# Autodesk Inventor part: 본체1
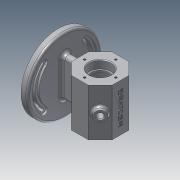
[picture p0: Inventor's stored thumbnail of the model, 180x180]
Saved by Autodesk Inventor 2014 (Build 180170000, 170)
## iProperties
Created: 2017-06
Part Number: 본체1
Material: 알루미늄 6061
Document SubType Name: Modeling
Designer: Administrator
Mass: 555.974 g
Surface Area: 564.009 cm^2
Volume: 205.157 cm^3
Density: 2.71 g/cm^3
Appearance: 알루미늄 - 평지
Author: Administrator
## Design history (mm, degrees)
sketch "스케치1"
  geometry: L1 (12.426, 30)-(30, 12.426); L2 (30, 12.426)-(30, -12.426); L3 (30, -12.426)-(12.426, -30); L4 (12.426, -30)-(-12.426, -30); L5 (-12.426, -30)-(-30, -12.426); L6 (-30, -12.426)-(-30, 12.426); L7 (-30, 12.426)-(-12.426, 30); L8 (-12.426, 30)-(12.426, 30); A1 r 30 centre (0, 0) between (0, 30) and (0, -30); 3 further points
  constraints: 16 end point, 4 midpoint, 4 point on circle, 4 tangent, 1 centre point, 1 coincident, 1 horizontal alignment
  dimensions: "d0" = 60 diameter of A1; "d74" = 60 distance between parallel lines of L3 L7; "d75" = 60 distance between parallel lines of L1 L5; "d76" = 24.85281 distance of L1.start L7.end; "d77" = 17.57359 horizontal distance of L6.end L7.end
extrude "돌출1" new body sketch "스케치1" stored distance "d1" = 70; taper "d2" = 0 deg
node "작업 평면1"
sketch "스케치3"
  geometry: L1 (0, 24.853)-(0, 42.426) reference; L2 (0, 42.426)-(70, 42.426) reference; 2 further points
  constraints: 1 other
  dimensions: "d4" = 35 distance from line of L1 point (35, 12.426); "d5" = 30 distance from line of L2 point (35, 12.426)
feature "엠보싱1" sketch "스케치3" dims "d6" = 0.5, "d7" = 0
sketch "스케치4"
  geometry: C1 r 8 at (12.426, 35); 1 further point
  constraints: 1 centre point, 1 coincident
  dimensions: "d8" = 16 diameter of C1
extrude "돌출2" join sketch "스케치4" distance "d9" = 7; taper "d10" = 0 deg
node "작업 평면2"
sketch "스케치6"
  geometry: C1 r 55 at (0, 0); 1 further point
  constraints: 1 centre point, 1 coincident
  dimensions: "d12" = 110 diameter of C1
extrude "돌출3" join sketch "스케치6" distance "d13" = 10; taper "d14" = 0 deg
sketch "스케치7"
  geometry: L1 (17.688, 29)-(52, 29); L2 (52, 29)-(52, -29); L3 (52, -29)-(17.688, -29); L4 (17.688, -29)-(17.688, 29); L5 (52, 55)-(52, -55) reference; 3 further points
  constraints: 8 end point, 2 coincident, 2 midpoint, 2 parallel, 1 horizontal, 1 perpendicular
  dimensions: "d15" = 58 distance between parallel lines of L3 L1
extrude "돌출4" join sketch "스케치7" stored distance "d16" = 10; taper "d17" = 0 deg
fillet "모깎기1" dims "d18" = 5
fillet "모깎기2" dims "d19" = 5
fillet "모깎기3" dims "d20" = 5
sketch "스케치9"
  geometry: L1 (0, 0)-(30.406, 30.406); L2 (0, 0)-(-30.406, 30.406); L3 (0, 0)-(30.406, -30.406); L4 (0, 0)-(-30.406, -30.406); C1 r 55 at (0, 0) reference; A1 r 43 centre (0, 0) between (30.406, 30.406) and (-30.406, 30.406); A2 r 48 centre (0, 0) between (33.941, 33.941) and (-33.941, 33.941); A3 r 38 centre (0, 0) between (26.87, 26.87) and (-26.87, 26.87); A4 r 5 centre (30.406, 30.406) between (26.87, 26.87) and (33.941, 33.941); A5 r 5 centre (-30.406, 30.406) between (-33.941, 33.941) and (-26.87, 26.87); A6 r 43 centre (0, 0) between (-30.406, -30.406) and (30.406, -30.406); A7 r 48 centre (0, 0) between (-33.941, -33.941) and (33.941, -33.941); A8 r 38 centre (0, 0) between (-26.87, -26.87) and (26.87, -26.87); A9 r 5 centre (-30.406, -30.406) between (-26.87, -26.87) and (-33.941, -33.941); A10 r 5 centre (30.406, -30.406) between (33.941, -33.941) and (26.87, -26.87); 2 further points
  constraints: 22 point on circle, 10 centre point, 8 end point, 8 tangent, 2 coincident, 2 vertical alignment
  dimensions: "d26" = 90 deg angle of L1 L2; "d27" = 90 deg angle of L4 L3; "d29" = 43 radius of A6; "d30" = 38 radius of A3; "d31" = 38 radius of A8; "d73" = 86 diameter of A1
extrude "돌출5" cut sketch "스케치9" distance "d32" = 3; taper "d33" = 0 deg
sketch "스케치10"
  geometry: C1 r 55 at (0, 0) reference; A1 r 5 centre (-30.406, 30.406) between (-33.941, 33.941) and (-26.87, 26.87) reference; A2 r 5 centre (30.406, 30.406) between (26.87, 26.87) and (33.941, 33.941) reference; A3 r 5 centre (30.406, -30.406) between (33.941, -33.941) and (26.87, -26.87) reference; A4 r 5 centre (-30.406, -30.406) between (-26.87, -26.87) and (-33.941, -33.941) reference; A5 r 43 centre (0, 0) between (30.406, 30.406) and (-30.406, 30.406); A6 r 45 centre (0, 0) between (31.82, 31.82) and (-31.82, 31.82); A7 r 41 centre (0, 0) between (28.991, 28.991) and (-28.991, 28.991); A8 r 2 centre (30.406, 30.406) between (28.991, 28.991) and (31.82, 31.82); A9 r 2 centre (-30.406, 30.406) between (-31.82, 31.82) and (-28.991, 28.991); A10 r 43 centre (0, 0) between (-30.406, -30.406) and (30.406, -30.406); A11 r 45 centre (0, 0) between (-31.82, -31.82) and (31.82, -31.82); A12 r 41 centre (0, 0) between (-28.991, -28.991) and (28.991, -28.991); A13 r 2 centre (-30.406, -30.406) between (-28.991, -28.991) and (-31.82, -31.82); A14 r 2 centre (30.406, -30.406) between (31.82, -31.82) and (28.991, -28.991)
  constraints: 20 point on circle, 10 centre point, 8 tangent, 2 coincident
  dimensions: "d34" = 2 radius of A9; "d35" = 2 radius of A13
extrude "돌출6" cut sketch "스케치10" distance "d36" = 10; taper "d37" = 0 deg
sketch "스케치13"
  geometry: L1 (0, -35)-(-16, -35); L2 (-16, -35)-(-16, -23); L3 (-16, -23)-(0, -23); L4 (0, -23)-(0, -35); L5 (0, -23)-(-14, -23); L6 (-14, -23)-(-14, -20); L7 (-14, -20)-(0, -20); L8 (0, -20)-(0, -23); L9 (0, -20)-(-25, -20); L10 (-25, -20)-(-25, 20); L11 (-25, 20)-(0, 20); L12 (0, 20)-(0, -20); L13 (0, 20)-(-14, 20); L14 (-14, 20)-(-14, 23); L15 (-14, 23)-(0, 23); L16 (0, 23)-(0, 20); L17 (0, 23)-(-16, 23); L18 (-16, 23)-(-16, 35); L19 (-16, 35)-(0, 35); L20 (0, 35)-(0, 23); L21 (12.426, 35)-(-12.426, 35) reference; L22 (-12.426, -35)-(12.426, -35) reference; 1 further point
  constraints: 40 end point, 10 parallel, 5 horizontal, 5 perpendicular, 3 midpoint
  dimensions: "d38" = 32 diameter of L2 L4; "d39" = 28 diameter of L6 L8; "d40" = 50 diameter of L10 L12; "d41" = 28 diameter of L14 L16; "d42" = 32 diameter of L18 L20; "d43" = 12 distance between parallel lines of L1 L3; "d44" = 12 distance between parallel lines of L19 L15; "d45" = 40 distance between parallel lines of L13 L9; "d46" = 3 distance between parallel lines of L15 L13
revolve "회전1" sketch "스케치13" stored, may be unused: angle "d47" = 90 deg
chamfer "모따기1" distance "d48" = 1; stored, may be unused: second distance "d49" = 2, angle "d50" = 45 deg
fillet "모깎기4" dims "d51" = 3
fillet "모깎기5" dims "d52" = 0.3
sketch "스케치14" dims "d53" = 46
  geometry: C1 r 17 at (0, 0) reference; 3 further points
  constraints: 2 coincident, 1 horizontal alignment, 2 other
hole "구멍1" sketch "스케치14" at (23, 0) diameter "d54" = 3.242; stored, may be unused: countersink angle "d58" = 90 deg, drill point angle "d60" = 118 deg; dims "d55" = 8, "d56" = 4, "d57" = 2, "d59" = 10
sketch "스케치15"
  geometry: C1 r 8 at (0, 0) reference; C2 r 4 at (0, 0)
  constraints: 1 centre point, 1 coincident
  dimensions: "d64" = 8 diameter of C2
extrude "돌출7" cut sketch "스케치15" stored distance "d65" = 7; taper "d66" = 0 deg
chamfer "모따기2" distance "d67" = 1; stored, may be unused: second distance "d68" = 2, angle "d69" = 45 deg
fillet "모깎기6" dims "d70" = 3
fillet "모깎기7" dims "d71" = 1
fillet "모깎기8" dims "d72" = 3
node "솔리드1"
pattern_circular "원형 패턴1" dims angle "d62" = 360 deg
mirror "대칭1"
other parameters: "d3" = 5.25, "d11" = -62
